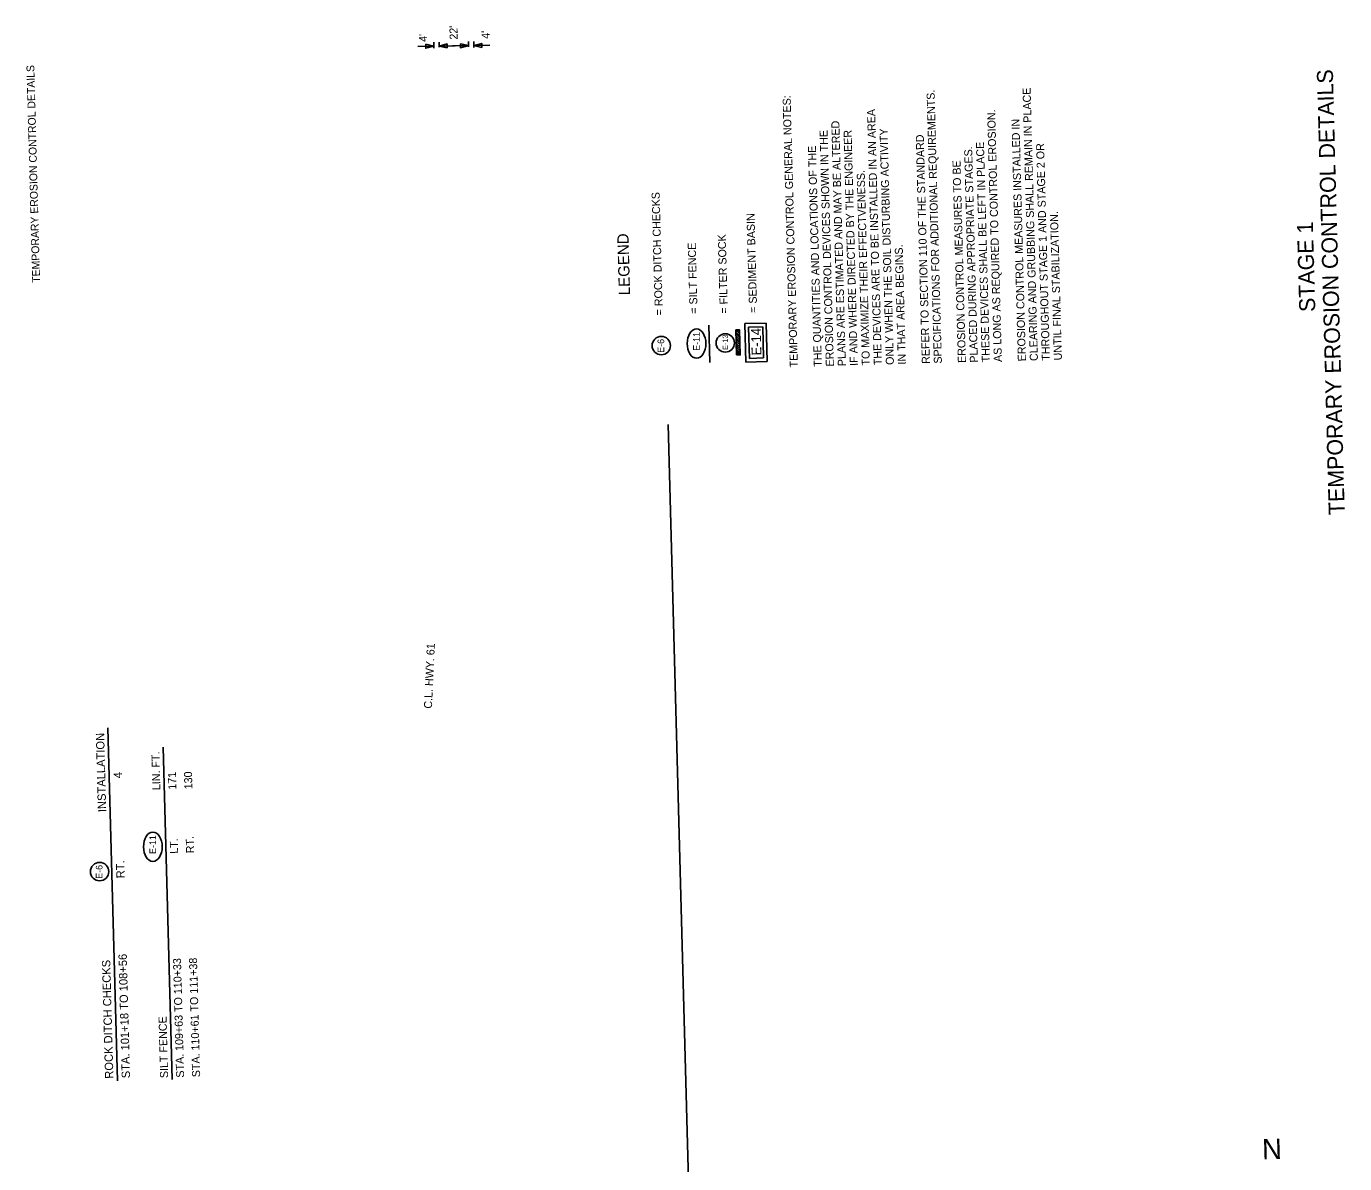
# Model space of a CAD drawing. Extents: x 1930579 to 1931596, y 596452 to 598574.
# Drawn here: x 1930608 to 1931596, y 597722 to 598574 of the extents above; entities that cross this region are included whole.
import ezdxf

# ---------------------------------------------------------------- set-up
doc = ezdxf.new("R2010")
doc.units = 0
for name, color, linetype in [('Default', 7, 'Continuous'), ('S_BASELINE', 7, 'Continuous'), ('S_BRIDGE', 7, 'Continuous'), ('S_EDGE_CONCRETE', 7, 'Continuous')]:
    doc.layers.add(name, color=color, linetype=linetype)

msp = doc.modelspace()

# ---------------------------------------------------------------- linework, layer by layer
at = {"layer": 'Default'}
msp.add_line((1930676.01, 597783.51), (1930668.89, 598048.46), dxfattribs=at)
at = {"layer": 'S_BASELINE'}
msp.add_line((1931105.18, 597672.96), (1931089, 598275.82), dxfattribs=at)
at = {"layer": 'S_BRIDGE'}
for p, q in [((1930913.17, 598558.16), (1930913.1, 598562.55)), ((1930917.17, 598558.69), (1930917.1, 598562.61)), ((1930939.16, 598559.05), (1930939.1, 598562.96)), ((1930943.17, 598558.62), (1930943.1, 598563.03)), ((1930913.15, 598559.55), (1930901.15, 598559.36)), ((1930917.15, 598559.61), (1930939.15, 598559.96)), ((1930929.15, 598559.8), (1930917.15, 598559.61)), ((1930939.15, 598559.96), (1930927.15, 598559.77)), ((1930955.15, 598560.22), (1930943.15, 598560.03)), ((1930716.99, 597784.61), (1930710.3, 598033.87))]:
    msp.add_line(p, q, dxfattribs=at)
for points in [[(1930907.13, 598560.95), (1930913.15, 598559.55), (1930907.18, 598557.95)], [(1930923.17, 598558.21), (1930917.15, 598559.61), (1930923.13, 598561.21)], [(1930923.17, 598558.21), (1930917.15, 598559.61), (1930923.13, 598561.21)], [(1930933.13, 598561.37), (1930939.15, 598559.96), (1930933.17, 598558.37)], [(1930933.13, 598561.37), (1930939.15, 598559.96), (1930933.17, 598558.37)], [(1930949.17, 598558.62), (1930943.15, 598560.03), (1930949.12, 598561.62)]]:
    msp.add_lwpolyline(points, close=True, dxfattribs=at)
at = {"layer": 'S_EDGE_CONCRETE'}
for p, q in [((1931142.53, 598343.8), (1931139.67, 598346.51)), ((1931142.57, 598342.39), (1931139.71, 598345.1)), ((1931142.61, 598340.98), (1931139.75, 598343.69)), ((1931142.5, 598345.22), (1931140.9, 598346.73)), ((1931142.46, 598346.63), (1931142.31, 598346.77)), ((1931146.42, 598351.49), (1931162.41, 598351.93)), ((1931147.19, 598322.66), (1931146.42, 598351.49)), ((1931149.2, 598348.87), (1931159.78, 598349.15)), ((1931149.82, 598325.43), (1931149.2, 598348.87)), ((1931160.41, 598325.72), (1931159.78, 598349.15)), ((1931163.19, 598323.09), (1931162.41, 598351.93)), ((1931142.65, 598339.56), (1931139.79, 598342.27)), ((1931142.69, 598338.15), (1931139.83, 598340.86)), ((1931142.72, 598336.73), (1931139.86, 598339.44)), ((1931142.76, 598335.32), (1931139.9, 598338.03)), ((1931142.8, 598333.91), (1931139.94, 598336.62)), ((1931142.84, 598332.49), (1931139.98, 598335.2)), ((1931142.87, 598331.08), (1931140.01, 598333.79)), ((1931142.91, 598329.67), (1931140.05, 598332.38)), ((1931142.95, 598328.25), (1931140.09, 598330.96)), ((1931141.76, 598328.01), (1931140.13, 598329.55)), ((1931140.34, 598327.97), (1931140.17, 598328.14)), ((1931149.82, 598325.43), (1931160.41, 598325.72)), ((1931147.19, 598322.66), (1931163.19, 598323.09))]:
    msp.add_line(p, q, dxfattribs=at)
msp.add_lwpolyline([(1931120.12, 598322.43), (1931119.36, 598350.23)], dxfattribs=at)
msp.add_lwpolyline([(1931140.17, 598327.96), (1931139.67, 598346.7), (1931142.45, 598346.77), (1931142.96, 598328.04)], close=True, dxfattribs=at)
for centre in [(1931131.67, 598336.95), (1931083.74, 598335), (1930662.65, 597940.52)]:
    msp.add_circle(centre, 6.88, dxfattribs=at)
for centre in [(1931110.16, 598336.48), (1930702.61, 597959.15)]:
    msp.add_ellipse(centre, major_axis=(0, 10.96), ratio=0.638788, dxfattribs=at)

# ---------------------------------------------------------------- texts
at = {"layer": 'Default'}
for s, p in [('INSTALLATION', (1930667.66, 597985.19)), ('4', (1930679.48, 598010.52)), ('RT.', (1930681.49, 597935.55)), ('STA. 101+18 TO 108+56', (1930685.52, 597785.6)), ('ROCK DITCH CHECKS', (1930673.02, 597785.27))]:
    msp.add_text(s, height=6.25, rotation=91.53769, dxfattribs=at).set_placement(p)
at = {"layer": 'S_BASELINE'}
for s, height, rotation, p in [('TEMPORARY EROSION CONTROL DETAILS', 5.862, 91.53769, (1930618.06, 598382.18)), ('TEMPORARY EROSION CONTROL GENERAL NOTES:', 6, 91.53769, (1931186.12, 598318.67)), ('SPECIFICATIONS FOR ADDITIONAL REQUIREMENTS.', 6, 91.53769, (1931294.08, 598321.56)), ('CLEARING AND GRUBBING SHALL REMAIN IN PLACE ', 6, 91.53769, (1931366.05, 598323.5)), ('THE DEVICES ARE TO BE INSTALLED IN AN AREA ', 6, 91.53769, (1931249.09, 598320.36)), ('AS LONG AS REQUIRED TO CONTROL EROSION.', 6, 91.53769, (1931339.06, 598322.77)), ('PLANS ARE ESTIMATED AND MAY BE ALTERED ', 6, 91.53769, (1931222.1, 598319.63)), ('EROSION CONTROL MEASURES INSTALLED IN', 6, 91.53769, (1931357.05, 598323.25)), ('EROSION CONTROL DEVICES SHOWN IN THE ', 6, 91.53769, (1931213.11, 598319.39)), ('IF AND WHERE DIRECTED BY THE ENGINEER ', 6, 91.53769, (1931231.1, 598319.87)), ('ONLY WHEN THE SOIL DISTURBING ACTIVITY', 6, 91.53769, (1931258.09, 598320.6)), ('REFER TO SECTION 110 OF THE STANDARD ', 6, 91.53769, (1931285.08, 598321.32)), ('THE QUANTITIES AND LOCATIONS OF THE', 6, 91.53769, (1931204.11, 598319.15)), ('PLACED DURING APPROPRIATE STAGES. ', 6, 91.53769, (1931321.07, 598322.29)), ('THESE DEVICES SHALL BE LEFT IN PLACE ', 6, 91.53769, (1931330.06, 598322.53)), ('THROUGHOUT STAGE 1 AND STAGE 2 OR ', 6, 91.53769, (1931375.05, 598323.74)), ('EROSION CONTROL MEASURES TO BE', 6, 91.53769, (1931312.07, 598322.05)), ('TO MAXIMIZE THEIR EFFECTVENESS. ', 6, 91.53769, (1931240.1, 598320.11)), ('UNTIL FINAL STABILIZATION.', 6, 91.53769, (1931384.05, 598323.98)), ('IN THAT AREA BEGINS.', 6, 91.53769, (1931267.09, 598320.84)), ('N', 15.38, 1.53769, (1931534.27, 597724.62))]:
    msp.add_text(s, height=height, rotation=rotation, dxfattribs=at).set_placement(p)
at = {"layer": 'S_BRIDGE'}
for s, height, rotation, p in [("22'", 6, 91.53769, (1930931.14, 598564.51)), ("4'", 6, 91.53769, (1930955.04, 598565.15)), ("4'", 6, 91.53769, (1930908.14, 598562.83)), ('TEMPORARY EROSION CONTROL DETAILS', 12, 91.53769, (1931596.09, 598208.09)), ('STAGE 1', 12, 91.53769, (1931574, 598360.36)), ('C.L. HWY. 61', 6, 87.3383, (1930911.76, 598062.62)), ('LIN. FT.', 6, 91.53769, (1930708.27, 598001.67)), ('171', 6, 91.53769, (1930720.26, 598001.99)), ('130', 6, 91.53769, (1930732.26, 598002.31)), ('LT.', 6, 91.53769, (1930721.55, 597954)), ('RT.', 6, 91.53769, (1930733.55, 597954.33)), ('STA. 109+63 TO 110+33', 6, 91.53769, (1930726.06, 597786.07)), ('STA. 110+61 TO 111+38', 6, 91.53769, (1930738.06, 597786.39)), ('SILT FENCE', 6, 91.53769, (1930714.06, 597785.74))]:
    msp.add_text(s, height=height, rotation=rotation, dxfattribs=at).set_placement(p)
at = {"layer": 'S_EDGE_CONCRETE'}
for s, height, rotation, p in [('= ROCK DITCH CHECKS', 6, 91.53769, (1931084.92, 598357.73)), ('= SEDIMENT BASIN', 6, 91.53769, (1931155.58, 598359.63)), ('LEGEND', 8.439, 91.53769, (1931060.37, 598372.86)), ('= FILTER SOCK', 6, 91.53769, (1931133.63, 598359.04)), ('= SILT FENCE', 6, 91.53769, (1931110.95, 598358.96)), ('E-11', 4.999, 90, (1931112.62, 598331.07)), ('E-14', 7.303, 91.53628, (1931158.78, 598327.69)), ('E-6 ', 4.999, 90, (1931085.91, 598329.59)), ('E-13', 4, 90, (1931133.67, 598331.67)), ('E-11', 5, 90, (1930705.07, 597953.74)), ('E-6 ', 4.999, 90, (1930664.83, 597935.11))]:
    msp.add_text(s, height=height, rotation=rotation, dxfattribs=at).set_placement(p)

doc.saveas('drawing.dxf')
